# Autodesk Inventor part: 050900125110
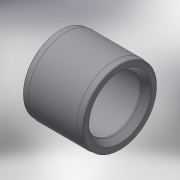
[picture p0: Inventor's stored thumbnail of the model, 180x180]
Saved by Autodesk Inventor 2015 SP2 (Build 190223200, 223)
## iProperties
Created: 2017-11
Part Number: 050900125110
Material: Generic
Description: PLASSON BUSHING-CEMENT PVC 125-110
Document SubType Name: Modeling
Designer: KIM
Density: 1 g/cm^3
Appearance: Default
Author: KIM
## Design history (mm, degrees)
derived "050900.ipt"
feature "Solid1::050900.ipt"
tag "TaggingFeature1"
body "Solid1"
other parameters: "d1" = 125, "d2" = 61, "d3" = 69, "d7" = 6.9, "d11" = 6.9, "d12" = 1.25, "d14" = 1.25, "d15" = 6.9, "d17" = 1.25, "d18" = 1.25, "d19" = 97.9, "d20" = 1.6, "d21" = 8.13, "D_" = 125, "L_" = 69, "l_" = 61, "z_" = 2
